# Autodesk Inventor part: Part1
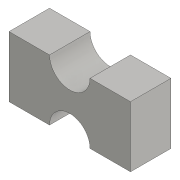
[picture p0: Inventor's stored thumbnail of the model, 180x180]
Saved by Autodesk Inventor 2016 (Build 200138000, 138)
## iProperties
Created: 2015-05
Part Number: Part1
Material: Generic
Document SubType Name: Modeling
Designer: Sandeep
Density: 1 g/cm^3
Appearance: Default
Author: Sandeep
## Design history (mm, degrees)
sketch "Sketch1"
  geometry: L1 (-30, -15)-(-10, -15); L2 (10, -15)-(30, -15); L3 (30, -15)-(30, 15); L4 (30, 15)-(10, 15); L5 (-10, 15)-(-30, 15); L6 (-30, 15)-(-30, -15); L7 (0, 32.136)-(0, -32.65); L8 (0, 0)-(-56.58, 0); A1 r 10 centre (0, -15) between (10, -15) and (-10, -15); A2 r 10 centre (0, 15) between (-10, 15) and (10, 15)
  constraints: 16 end point, 9 point on line, 4 point on circle, 3 perpendicular, 2 centre point, 2 horizontal, 1 equal radius, 1 vertical, 2 other
  dimensions: "d3" = 60 distance between parallel lines of L3 L6 (= LEN); "d4" = 30 distance between parallel lines of L1 L5 (= WID); "d5" = 10 radius of A2 (= RAD)
extrude "Extrusion1" new body sketch "Sketch1" distance "d6" = 20 (= EXT); taper "d7" = 0 deg
body "Solid1"
other parameters: "LEN" = 60 [user parameter; used in 4 equation terms], "WID" = 30 (= 0.5 x LEN) [user parameter; used in 1 equation term], "RAD" = 10 (= 0.166667 x LEN) [user parameter; used in 1 equation term], "EXT" = 20 (= 0.333333 x LEN) [user parameter; used in 1 equation term]
